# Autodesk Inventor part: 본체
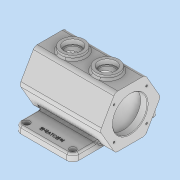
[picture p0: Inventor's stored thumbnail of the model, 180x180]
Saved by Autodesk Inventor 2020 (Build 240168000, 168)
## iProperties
Created: 2021-06
Part Number: 본체
Material: 일반
Document SubType Name: Modeling
Designer: PC2-03
Density: 1 g/cm^3
Appearance: 기본값
Mass: 552.279 g
Surface Area: 1106.53 cm^2
Volume: 552.279 cm^3
Author: PC2-03
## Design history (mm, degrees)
sketch "스케치1"
  geometry: L1 (-50, 75)-(50, 75); L2 (50, 75)-(50, -75); L3 (50, -75)-(-50, -75); L4 (-50, -75)-(-50, 75); 3 further points
  constraints: 8 end point, 2 midpoint, 2 parallel, 1 horizontal, 1 horizontal alignment, 1 perpendicular, 1 vertical alignment
  dimensions: "d0" = 150 distance between parallel lines of L3 L1; "d1" = 100 distance of L2.end L3.end
extrude "돌출1" new body sketch "스케치1" distance "d2" = 12; taper "d3" = 0 deg
sketch "스케치5" dims "d7" = 105
  geometry: L1 (-75, 0)-(75, 0) reference; L2 (26.25, 95.466)-(52.5, 50); L3 (52.5, 50)-(26.25, 4.534); L4 (26.25, 4.534)-(-26.25, 4.534); L5 (-26.25, 4.534)-(-52.5, 50); L6 (-52.5, 50)-(-26.25, 95.466); L7 (-26.25, 95.466)-(26.25, 95.466); 4 further points
  constraints: 12 end point, 1 coincident, 1 horizontal, 1 midpoint, 1 vertical alignment, 16 other
  dimensions: "d6" = 50 distance from line of point (0, 50) L1
extrude "돌출2" join sketch "스케치5" distance "d8" = 65; taper "d10" = 0 deg; dims "d9" = 75, "d11" = 0
node "작업 평면1"
sketch "스케치6"
  geometry: L1 (-75, -26.25)-(-75, 26.25) reference; C1 r 20 at (-35, 0); C2 r 20 at (25, 0); 1 further point
  constraints: 2 centre point, 2 horizontal alignment
  dimensions: "d13" = 40 distance from line of C1.centre L1; "d14" = 40 diameter of C1; "d15" = 40 diameter of C2; "d16" = 60 distance of C1.centre C2.centre
extrude "돌출3" join sketch "스케치6" stored distance "d17" = 65; taper "d18" = 0 deg
sketch "스케치7"
  geometry: C1 r 20 at (0, 0) reference; C2 r 20 at (60, 0) reference; 3 further points
  constraints: 2 coincident
hole "구멍1" sketch "스케치7" at (0, 0), (60, 0) diameter "d19" = 30; stored, may be unused: countersink angle "d23" = 90 deg, drill point angle "d25" = 0 deg; dims "d20" = 6, "d21" = 4, "d22" = 2, "d24" = 8
sketch "스케치8"
  geometry: L1 (75, 50)-(-65, 50); L2 (-50, 0)-(50, 0) reference; L3 (75, 95.466)-(75, 50) reference; L4 (75, 50)-(75, 80); L5 (75, 80)-(63, 80); L6 (63, 80)-(63, 87.5); L7 (63, 87.5)-(-53, 87.5); L8 (-53, 87.5)-(-53, 80); L9 (-53, 80)-(-65, 80); L10 (-65, 50)-(-65, 95.466) reference; L11 (-65, 50)-(-65, 80); 1 further point
  constraints: 16 end point, 6 point on line, 4 perpendicular, 2 horizontal
  dimensions: "d26" = 50 distance between parallel lines of L2 L1; "d27" = 12 distance of L4.end L5.end; "d28" = 12 distance of L8.end L9.end; "d29" = 60 diameter of L5 L1; "d30" = 75 diameter of L7 L1
revolve "회전1" sketch "스케치8" stored, may be unused: angle "d31" = 90 deg
sketch "스케치9"
  geometry: C1 r 15 at (0, 0) reference; 2 further points
  constraints: 1 coincident
hole "구멍2" sketch "스케치9" at (0, 0) diameter "d32" = 25; stored, may be unused: countersink angle "d36" = 90 deg, drill point angle "d38" = 0 deg; dims "d33" = 6, "d34" = 4, "d35" = 2, "d37" = 8
sketch "스케치10"
  geometry: C1 r 15 at (0, 0) reference; 2 further points
  constraints: 1 coincident
hole "구멍3" sketch "스케치10" at (0, 0) diameter "d39" = 25; stored, may be unused: countersink angle "d43" = 90 deg, drill point angle "d45" = 0 deg; dims "d40" = 6, "d41" = 4, "d42" = 2, "d44" = 8
sketch "스케치11"
  geometry: L1 (50, 0)-(50, -40); L2 (50, 0)-(78.284, -28.284); C1 r 30 at (50, 0) reference; A1 r 40 centre (50, 0) between (50, -40) and (78.284, -28.284); 2 further points
  constraints: 4 end point, 2 point on circle, 1 centre point, 1 coincident, 1 concentric, 1 vertical
  dimensions: "d47" = 80 diameter of A1; "d48" = 45 deg angle of L2 L1
hole "구멍4" sketch "스케치11" at (78.284, -28.284) diameter "d49" = 3.242; stored, may be unused: countersink angle "d53" = 90 deg, drill point angle "d55" = 118 deg; dims "d50" = 8, "d51" = 4, "d52" = 2, "d54" = 10
sketch "스케치12" dims "d59" = 80
  geometry: C1 r 30 at (-50, 0) reference; 3 further points
  constraints: 2 vertical alignment, 3 other
hole "구멍5" sketch "스케치12" at (-50, -40) diameter "d60" = 3.242; stored, may be unused: countersink angle "d64" = 90 deg, drill point angle "d66" = 118 deg; dims "d61" = 8, "d62" = 4, "d63" = 2, "d65" = 10
fillet "모깎기1" dims "d70" = 10
sketch "스케치13"
  geometry: A1 r 10 centre (-40, 65) between (-40, 75) and (-50, 65) reference; 2 further points
  constraints: 1 coincident
hole "구멍6" sketch "스케치13" at (-40, 65) diameter "d71" = 11; stored, may be unused: countersink angle "d75" = 90 deg, drill point angle "d77" = 0 deg; dims "d72" = 8, "d73" = 4, "d74" = 2, "d76" = 10
fillet "모깎기2" dims "d90" = 8
chamfer "모따기1" distance "d91" = 1; stored, may be unused: second distance "d92" = 2, angle "d93" = 45 deg
chamfer "모따기2" distance "d94" = 1; stored, may be unused: second distance "d95" = 2, angle "d96" = 45 deg
fillet "모깎기3" dims "d97" = 3
fillet "모깎기4" dims "d98" = 3
fillet "모깎기5" dims "d99" = 3
fillet "모깎기6" dims "d100" = 3
fillet "모깎기7" dims "d101" = 3
fillet "모깎기8" dims "d102" = 3
fillet "모깎기9" dims "d103" = 3
sketch "스케치15"
  geometry: L1 (20.739, 57.998)-(-20.739, 57.998); L2 (-20.739, 57.998)-(-20.739, 64.002); L3 (-20.739, 64.002)-(20.739, 64.002); L4 (20.739, 64.002)-(20.739, 57.998); L5 (20.739, 61)-(-20.739, 61); L6 (0, 57.998)-(0, 64.002); L7 (-50, 65)-(-50, 35.757) reference; L8 (40, 75)-(-40, 75) reference; 1 further point
  constraints: 4 end point, 4 midpoint, 1 horizontal, 2 other
  dimensions: "d104" = 50 distance between parallel lines of L7 L6; "d105" = 6.00407 distance of L1.end L2.end; "d106" = 41.47897 distance of L1.start L1.end; "d107" = 14 distance between parallel lines of L5 L8
feature "엠보싱1" sketch "스케치15" dims "d0" = 150, "d1" = 100, "d12" = 102.5, "d108" = 0.5, "d109" = 0
node "솔리드1"
pattern_circular "원형 패턴1" dims angle "d57" = 360 deg
pattern_circular "원형 패턴2" dims angle "d68" = 360 deg
pattern_linear "직사각형 패턴2" dims "d86" = 80, "d89" = 130
feature "A9D066F2-1C7D-4E18-AEED-F7BC21143FA4" dims "d71" = 11, "d72" = 8, "d73" = 4, "d74" = 2, "d75" = 90 deg, "d76" = 10, "d77" = 0
